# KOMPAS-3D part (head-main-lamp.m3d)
File: created 02.10.2016 09:40:27, last saved 05.10.2016 12:17:08.
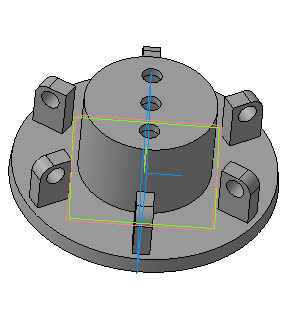
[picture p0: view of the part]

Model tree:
1. Эскиз:1
2. Операция вращения:1
     Угол 1 = 360
3. Эскиз:7
4. Операция выдавливания:2
     Расстояние 1 = 18
5. Эскиз:8
6. Вырезать элемент выдавливания:4
     Расстояние 1 = 6
7. Эскиз:9
8. Вырезать элемент выдавливания:5
     Расстояние 1 = 6
9. Эскиз:10
10. Вырезать элемент выдавливания:6
     Расстояние 1 = 6
11. Эскиз:11
12. Вырезать элемент выдавливания:7
     Расстояние 1 = 6
13. Эскиз:12
14. Вырезать элемент выдавливания:8
     Расстояние 1 = 6
15. Эскиз:13
16. Вырезать элемент выдавливания:9
     Расстояние 1 = 6
17. Скругление:1
     Радиус = 5
18. Эскиз:14
19. Вырезать элемент выдавливания:10
     Расстояние 2 = 81.5; Расстояние 1 = 81.5
20. Эскиз:15
21. Вырезать элемент выдавливания:11
     Расстояние 1 = 35.5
